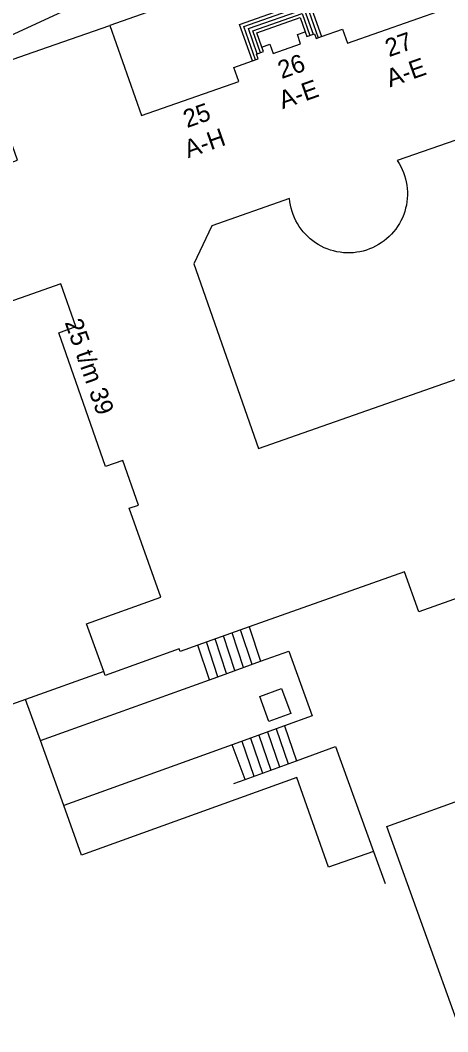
# Model space of a CAD drawing. Extents: x 122462 to 123306, y 485548 to 486417.
# Drawn here: x 122889.1 to 122924.9, y 485986.2 to 486070.8 of the extents above; entities that cross this region are included whole.
import ezdxf

# ---------------------------------------------------------------- set-up
doc = ezdxf.new("R2010")
doc.units = 0
for name, color, linetype in [('Level 1', 7, 'Continuous'), ('Level 17', 7, 'Continuous'), ('Level 19', 7, 'Continuous'), ('Level 2', 7, 'Continuous'), ('Level 22', 7, 'Continuous'), ('Level 23', 7, 'Continuous'), ('Level 30', 7, 'Continuous'), ('Level 31', 7, 'Continuous'), ('Level 33', 7, 'Continuous'), ('Level 58', 7, 'Continuous')]:
    doc.layers.add(name, color=color, linetype=linetype)

msp = doc.modelspace()

# ---------------------------------------------------------------- linework, layer by layer
at = {"layer": 'Level 1'}
msp.add_line((122908.263, 486020.04), (122903.973, 486018.522), dxfattribs=at)
for points in [[(122914.301, 486069.427), (122916.08, 486070.049), (122916.496, 486068.869), (122924.61, 486071.717), (122921.949, 486079.289)], [(122886.287, 486066.358), (122886.15, 486066.739), (122891.37, 486068.55), (122896.59, 486070.36)], [(122896.59, 486070.36), (122899.259, 486062.819), (122907.394, 486065.676), (122906.979, 486066.85), (122908.527, 486067.401)], [(122909.333, 486068.554), (122909.991, 486068.785), (122910.263, 486068.009), (122912.568, 486068.818), (122912.296, 486069.594), (122912.955, 486069.825)], [(122912.955, 486069.825), (122913.088, 486069.445), (122913.715, 486069.665), (122913.854, 486069.27), (122914.301, 486069.427)], [(122908.527, 486067.401), (122909.009, 486067.57), (122908.871, 486067.964), (122909.466, 486068.173), (122909.333, 486068.554)], [(122896.094, 486016.295), (122894.653, 486020.3), (122900.858, 486022.533), (122898.226, 486029.963), (122898.999, 486030.234), (122897.687, 486033.972), (122896.242, 486033.465), (122892.313, 486044.656), (122893.758, 486045.163), (122892.503, 486048.739), (122871.57, 486041.39), (122870.82, 486043.488), (122870.51, 486043.376), (122868.31, 486049.514), (122868.62, 486049.625), (122867.865, 486051.73), (122870.804, 486052.773), (122870.838, 486052.679), (122888.869, 486059.085), (122886.287, 486066.358)], [(122925.558, 486060.77), (122920.657, 486059.05), (122920.807, 486058.816), (122920.943, 486058.573), (122921.066, 486058.323), (122921.174, 486058.067), (122921.267, 486057.805), (122921.346, 486057.538), (122921.41, 486057.267), (122921.458, 486056.993), (122921.491, 486056.717), (122921.508, 486056.439), (122921.51, 486056.161), (122921.495, 486055.883), (122921.466, 486055.607), (122921.42, 486055.332), (122921.36, 486055.061), (122921.284, 486054.793), (122921.193, 486054.53), (122921.088, 486054.273), (122920.968, 486054.022), (122920.834, 486053.778), (122920.687, 486053.541), (122920.527, 486053.314), (122920.354, 486053.096), (122920.169, 486052.888), (122919.973, 486052.691), (122919.766, 486052.505), (122919.549, 486052.331), (122919.322, 486052.17), (122919.087, 486052.021), (122918.844, 486051.886), (122918.593, 486051.765), (122918.336, 486051.659), (122918.074, 486051.566), (122917.806, 486051.489), (122917.535, 486051.427), (122917.261, 486051.381), (122916.984, 486051.349), (122916.707, 486051.334), (122916.428, 486051.334), (122916.151, 486051.35), (122915.874, 486051.381), (122915.6, 486051.428), (122915.329, 486051.49), (122915.062, 486051.568), (122914.799, 486051.66), (122914.542, 486051.767), (122914.292, 486051.888), (122914.049, 486052.023), (122913.814, 486052.172), (122913.587, 486052.333), (122913.37, 486052.507), (122913.163, 486052.693), (122912.967, 486052.891), (122912.782, 486053.099), (122912.61, 486053.317), (122912.45, 486053.545), (122912.303, 486053.781), (122912.169, 486054.025), (122912.05, 486054.276), (122911.944, 486054.534), (122911.854, 486054.797), (122911.778, 486055.064), (122911.718, 486055.336), (122911.673, 486055.61), (122911.643, 486055.887), (122905.146, 486053.607), (122903.615, 486050.421), (122909.043, 486034.951)], [(122909.043, 486034.951), (122934.172, 486043.77)], [(122928.903, 485987.214), (122925.986, 485986.162), (122919.786, 486003.35), (122927.526, 486006.135), (122927.453, 486006.334), (122927.763, 486006.439), (122927.347, 486007.679), (122929.213, 486008.337), (122929.077, 486008.687), (122930.344, 486011.27), (122933.003, 486012.254), (122935.587, 486011.038), (122935.716, 486010.68), (122937.315, 486011.257), (122932.421, 486024.831), (122922.45, 486021.312), (122921.27, 486024.643), (122908.263, 486020.04)], [(122903.973, 486018.522), (122902.47, 486017.99), (122902.394, 486018.197), (122896.21, 486015.972), (122896.094, 486016.295)]]:
    msp.add_lwpolyline(points, dxfattribs=at)
at = {"layer": 'Level 17'}
msp.add_line((122921.949, 486079.289), (122896.59, 486070.36), dxfattribs=at)
msp.add_lwpolyline([(122866.697, 486059.573), (122890.454, 486070.535), (122901.853, 486075.794), (122903.288, 486076.393), (122904.729, 486076.979), (122906.176, 486077.551), (122907.628, 486078.109), (122909.085, 486078.653), (122910.547, 486079.184), (122912.014, 486079.7), (122913.486, 486080.203), (122914.963, 486080.692), (122916.444, 486081.166), (122917.929, 486081.627), (122919.419, 486082.073), (122920.914, 486082.505), (122922.412, 486082.923), (122923.914, 486083.327), (122925.42, 486083.717)], dxfattribs=at)
at = {"layer": 'Level 19'}
msp.add_line((122890.786, 486010.52), (122889.546, 486013.97), dxfattribs=at)
msp.add_lwpolyline([(122918.678, 486001.241), (122914.911, 485999.925), (122912.259, 486007.431), (122894.234, 486000.941), (122892.738, 486005.1)], dxfattribs=at)
at = {"layer": 'Level 2'}
msp.add_lwpolyline([(122909.911, 486012.116), (122909.15, 486014.207), (122910.973, 486014.87), (122911.734, 486012.78), (122909.911, 486012.116)], dxfattribs=at)
at = {"layer": 'Level 22'}
for p, q in [((122890.786, 486010.52), (122904.93, 486015.617)), ((122911.23, 486011.761), (122906.84, 486010.18)), ((122892.738, 486005.1), (122890.786, 486010.52)), ((122906.84, 486010.18), (122892.738, 486005.1)), ((122907.93, 486007.28), (122912.227, 486008.838)), ((122906.984, 486006.937), (122907.93, 486007.28)), ((122918.678, 486001.241), (122919.641, 485998.58))]:
    msp.add_line(p, q, dxfattribs=at)
for points in [[(122909.213, 486017.158), (122911.582, 486018.011), (122913.534, 486012.591), (122911.23, 486011.761)], [(122904.93, 486015.617), (122905.644, 486015.872), (122909.213, 486017.158)], [(122912.227, 486008.838), (122915.499, 486010.024), (122918.678, 486001.241)]]:
    msp.add_lwpolyline(points, dxfattribs=at)
at = {"layer": 'Level 23'}
for p, q in [((122896.094, 486016.295), (122889.546, 486013.97)), ((122889.546, 486013.97), (122878.968, 486010.214))]:
    msp.add_line(p, q, dxfattribs=at)
at = {"layer": 'Level 30'}
msp.add_lwpolyline([(122909.333, 486068.554), (122908.913, 486069.752), (122912.534, 486071.023), (122912.955, 486069.825)], dxfattribs=at)
at = {"layer": 'Level 31'}
for p, q in [((122908.263, 486020.04), (122909.213, 486017.158)), ((122904.93, 486015.617), (122903.973, 486018.522)), ((122911.23, 486011.761), (122912.227, 486008.838)), ((122907.93, 486007.28), (122906.84, 486010.18))]:
    msp.add_line(p, q, dxfattribs=at)
msp.add_lwpolyline([(122908.527, 486067.401), (122907.456, 486070.449), (122913.23, 486072.476), (122914.301, 486069.427)], dxfattribs=at)
at = {"layer": 'Level 33'}
for p, q in [((122907.785, 486016.643), (122906.832, 486019.534)), ((122908.498, 486016.9), (122907.547, 486019.787)), ((122905.644, 486015.872), (122904.687, 486018.775)), ((122906.358, 486016.129), (122905.402, 486019.028)), ((122907.071, 486016.386), (122906.117, 486019.281)), ((122909.082, 486010.987), (122910.08, 486008.059)), ((122909.798, 486011.245), (122910.796, 486008.319)), ((122910.514, 486011.503), (122911.512, 486008.578)), ((122907.65, 486010.471), (122908.65, 486007.541)), ((122908.366, 486010.729), (122909.365, 486007.8))]:
    msp.add_line(p, q, dxfattribs=at)
for points in [[(122908.801, 486067.497), (122907.826, 486070.271), (122913.052, 486072.106), (122914.027, 486069.331)], [(122908.936, 486067.987), (122908.196, 486070.094), (122912.875, 486071.737), (122913.615, 486069.63)], [(122909.21, 486068.083), (122908.565, 486069.916), (122912.697, 486071.367), (122913.341, 486069.534)]]:
    msp.add_lwpolyline(points, dxfattribs=at)

# ---------------------------------------------------------------- texts
at = {"layer": 'Level 58'}
for s, rotation, p in [('27', 19.33805, (122919.962, 486067.704)), ('26', 19.33805, (122910.975, 486065.874)), ('A-E', 19.33805, (122920.047, 486065.18)), ('A-E', 19.33805, (122911.06, 486063.35)), ('25', 19.33805, (122903.062, 486061.772)), ('A-H', 19.33805, (122903.147, 486059.249)), ('25 t/m 39', 289.34546, (122892.804, 486045.526))]:
    msp.add_text(s, height=1.5, rotation=rotation, dxfattribs=at).set_placement(p)

doc.saveas('drawing.dxf')
